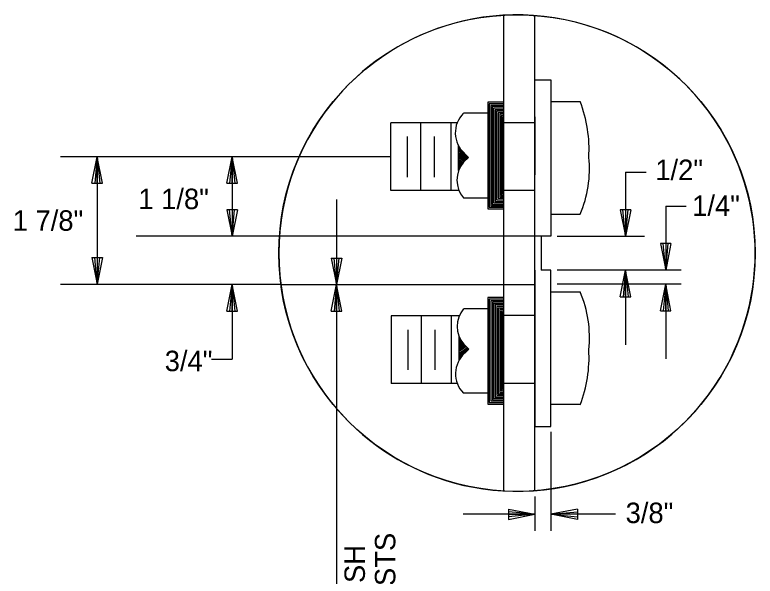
# Model space of a CAD drawing. Extents: x 12.3 to 19.6, y 18.8 to 29.6.
# Drawn here: x 12.414 to 14.586, y 27.691 to 29.338 of the extents above; entities that cross this region are included whole.
import ezdxf

# ---------------------------------------------------------------- set-up
doc = ezdxf.new("R2010")
doc.units = 0
for name, color, linetype in [('BORD-LINE', 7, 'Continuous'), ('DETL-DIMS', 7, 'Continuous'), ('DETL-LINE', 7, 'Continuous')]:
    doc.layers.add(name, color=color, linetype=linetype)

msp = doc.modelspace()

# ---------------------------------------------------------------- linework, layer by layer
at = {"layer": 'BORD-LINE'}
msp.add_lwpolyline([(14.5857, 28.6389), (14.5853, 28.6633), (14.584, 28.6882), (14.5817, 28.7135), (14.5785, 28.7392), (14.5742, 28.7652), (14.5688, 28.7915), (14.5623, 28.818), (14.5547, 28.8447), (14.5459, 28.8715), (14.5358, 28.8982), (14.5245, 28.9249), (14.5119, 28.9515), (14.498, 28.9779), (14.4828, 29.0039), (14.4663, 29.0295), (14.4485, 29.0547), (14.4295, 29.0792), (14.4092, 29.1031), (14.3877, 29.1262), (14.365, 29.1485), (14.3413, 29.1698), (14.3164, 29.19), (14.2906, 29.2092), (14.2639, 29.2272), (14.2363, 29.244), (14.208, 29.2595), (14.1791, 29.2736), (14.1495, 29.2864), (14.1196, 29.2978), (14.0892, 29.3077), (14.0586, 29.3162), (14.0279, 29.3233), (13.997, 29.3289), (13.9663, 29.3331), (13.9356, 29.3359), (13.9052, 29.3374), (13.875, 29.3375), (13.8453, 29.3364), (13.8159, 29.334), (13.7871, 29.3305), (13.7589, 29.3258), (13.7313, 29.3201), (13.7044, 29.3134), (13.6782, 29.3057), (13.6528, 29.2972), (13.6281, 29.2879), (13.6042, 29.2779), (13.5812, 29.2672), (13.559, 29.2559), (13.5376, 29.244), (13.5166, 29.2314), (13.4957, 29.2178), (13.4749, 29.2032), (13.4543, 29.1876), (13.4339, 29.1709), (13.4138, 29.1531), (13.3941, 29.1342), (13.3749, 29.1143), (13.3561, 29.0932), (13.338, 29.0711), (13.3205, 29.048), (13.3038, 29.0237), (13.2879, 28.9985), (13.2729, 28.9724), (13.259, 28.9453), (13.2461, 28.9173), (13.2343, 28.8886), (13.2238, 28.859), (13.2145, 28.8289), (13.2066, 28.7981), (13.2, 28.7669), (13.1949, 28.7352), (13.1912, 28.7033), (13.189, 28.6711), (13.1882, 28.6389), (13.189, 28.6066), (13.1912, 28.5745), (13.1949, 28.5425), (13.2, 28.5109), (13.2066, 28.4796), (13.2145, 28.4489), (13.2238, 28.4187), (13.2343, 28.3892), (13.2461, 28.3605), (13.259, 28.3325), (13.2729, 28.3054), (13.2879, 28.2792), (13.3038, 28.254), (13.3205, 28.2298), (13.338, 28.2067), (13.3561, 28.1845), (13.3749, 28.1635), (13.3941, 28.1436), (13.4138, 28.1247), (13.4339, 28.1069), (13.4543, 28.0902), (13.4749, 28.0745), (13.4957, 28.0599), (13.5166, 28.0464), (13.5376, 28.0338), (13.559, 28.0219), (13.5812, 28.0106), (13.6042, 27.9999), (13.6281, 27.9899), (13.6528, 27.9806), (13.6782, 27.9721), (13.7044, 27.9644), (13.7313, 27.9577), (13.7589, 27.952), (13.7871, 27.9473), (13.8159, 27.9438), (13.8453, 27.9414), (13.875, 27.9403), (13.9052, 27.9404), (13.9356, 27.9418), (13.9663, 27.9447), (13.997, 27.9489), (14.0279, 27.9545), (14.0586, 27.9616), (14.0892, 27.9701), (14.1196, 27.98), (14.1495, 27.9914), (14.1791, 28.0041), (14.208, 28.0183), (14.2363, 28.0338), (14.2639, 28.0505), (14.2906, 28.0685), (14.3164, 28.0877), (14.3413, 28.108), (14.365, 28.1293), (14.3877, 28.1516), (14.4092, 28.1747), (14.4295, 28.1985), (14.4485, 28.2231), (14.4663, 28.2482), (14.4828, 28.2739), (14.498, 28.2999), (14.5119, 28.3263), (14.5245, 28.3528), (14.5358, 28.3795), (14.5459, 28.4063), (14.5547, 28.4331), (14.5623, 28.4597), (14.5688, 28.4863), (14.5742, 28.5125), (14.5785, 28.5386), (14.5817, 28.5642), (14.584, 28.5895), (14.5853, 28.6144)], close=True, dxfattribs=at)
msp.add_circle((13.887, 28.6389), 0.6987, dxfattribs=at)
at = {"layer": 'DETL-DIMS'}
for p, q in [((13.5165, 28.9215), (12.5474, 28.9215)), ((12.6398, 28.8436), (12.6554, 28.9215)), ((12.6554, 28.9215), (12.6482, 28.8436)), ((12.6554, 28.8436), (12.6554, 28.9215)), ((12.671, 28.8436), (12.6554, 28.9215)), ((12.6554, 28.9215), (12.6632, 28.8436)), ((12.6554, 28.9215), (12.6554, 28.5465)), ((13.0355, 28.8436), (13.0511, 28.9215)), ((13.0511, 28.9215), (13.0439, 28.8436)), ((13.0511, 28.9215), (13.0511, 28.6882)), ((13.0511, 28.8436), (13.0511, 28.9215)), ((13.0667, 28.8436), (13.0511, 28.9215)), ((13.0511, 28.9215), (13.0589, 28.8436)), ((14.2056, 28.8763), (14.2056, 28.6882)), ((14.2056, 28.8763), (14.2656, 28.8763)), ((12.6398, 28.8436), (12.671, 28.8436)), ((13.0355, 28.8436), (13.0667, 28.8436)), ((13.3576, 28.7965), (13.3576, 27.1228)), ((13.0667, 28.7661), (13.0355, 28.7661)), ((13.0355, 28.7661), (13.0511, 28.6882)), ((13.0511, 28.6882), (13.0433, 28.7661)), ((13.0511, 28.7661), (13.0511, 28.6882)), ((13.0667, 28.7661), (13.0511, 28.6882)), ((13.0511, 28.6882), (13.0583, 28.7661)), ((14.2212, 28.7661), (14.19, 28.7661)), ((14.19, 28.7661), (14.2056, 28.6882)), ((14.2056, 28.6882), (14.1978, 28.7661)), ((14.2056, 28.7661), (14.2056, 28.6882)), ((14.2212, 28.7661), (14.2056, 28.6882)), ((14.2056, 28.6882), (14.2128, 28.7661)), ((14.3231, 28.7769), (14.3231, 28.5888)), ((14.3231, 28.7769), (14.3831, 28.7769)), ((13.9575, 28.6882), (12.7703, 28.6882)), ((14.0047, 28.6882), (14.261, 28.6882)), ((14.3387, 28.6667), (14.3075, 28.6667)), ((14.3075, 28.6667), (14.3231, 28.5888)), ((14.3231, 28.5888), (14.3153, 28.6667)), ((14.3231, 28.6667), (14.3231, 28.5888)), ((14.3387, 28.6667), (14.3231, 28.5888)), ((14.3231, 28.5888), (14.3303, 28.6667)), ((12.6398, 28.6256), (12.671, 28.6256)), ((12.6398, 28.6256), (12.6554, 28.5477)), ((12.6554, 28.5477), (12.6482, 28.6256)), ((12.6554, 28.6256), (12.6554, 28.5477)), ((12.671, 28.6256), (12.6554, 28.5477)), ((12.6554, 28.5477), (12.6632, 28.6256)), ((13.342, 28.6244), (13.3732, 28.6244)), ((13.342, 28.6244), (13.3576, 28.5465)), ((13.3576, 28.5465), (13.3504, 28.6244)), ((13.3576, 28.6244), (13.3576, 28.5465)), ((13.3732, 28.6244), (13.3576, 28.5465)), ((13.3576, 28.5465), (13.3654, 28.6244)), ((14.369, 28.5888), (14.0047, 28.5888)), ((14.19, 28.5109), (14.2056, 28.5888)), ((14.2056, 28.5888), (14.1984, 28.5109)), ((14.2056, 28.5109), (14.2056, 28.5888)), ((14.2212, 28.5109), (14.2056, 28.5888)), ((14.2056, 28.5888), (14.2134, 28.5109)), ((14.2056, 28.5888), (14.2056, 28.3697)), ((13.1944, 28.5465), (12.5474, 28.5465)), ((13.0355, 28.4686), (13.0511, 28.5465)), ((13.0511, 28.5465), (13.0439, 28.4686)), ((13.0511, 28.4686), (13.0511, 28.5465)), ((13.0667, 28.4686), (13.0511, 28.5465)), ((13.0511, 28.5465), (13.0589, 28.4686)), ((13.0511, 28.5465), (13.0511, 28.3274)), ((13.342, 28.4686), (13.3576, 28.5465)), ((13.3576, 28.5465), (13.3504, 28.4686)), ((13.3576, 28.4686), (13.3576, 28.5465)), ((13.3732, 28.4686), (13.3576, 28.5465)), ((13.3576, 28.5465), (13.3654, 28.4686)), ((14.369, 28.5477), (14.0047, 28.5477)), ((14.3075, 28.4698), (14.3231, 28.5477)), ((14.3231, 28.5477), (14.3159, 28.4698)), ((14.3231, 28.4698), (14.3231, 28.5477)), ((14.3387, 28.4698), (14.3231, 28.5477)), ((14.3231, 28.5477), (14.3309, 28.4698)), ((14.3231, 28.5477), (14.3231, 28.3286)), ((14.19, 28.5109), (14.2212, 28.5109)), ((13.0355, 28.4686), (13.0667, 28.4686)), ((13.342, 28.4686), (13.3732, 28.4686)), ((14.3075, 28.4698), (14.3387, 28.4698)), ((12.9911, 28.3274), (13.0511, 28.3274)), ((13.9863, 28.1145), (13.9863, 27.8243)), ((13.9395, 27.9253), (13.9395, 27.8243)), ((13.8616, 27.8884), (13.8616, 27.8572)), ((13.8616, 27.8884), (13.9395, 27.8728)), ((14.0642, 27.8884), (13.9863, 27.8728)), ((14.0642, 27.8884), (14.0642, 27.8572)), ((13.9395, 27.8728), (13.7286, 27.8728)), ((13.9395, 27.8728), (13.8616, 27.88)), ((13.8616, 27.8728), (13.9395, 27.8728)), ((13.8616, 27.8572), (13.9395, 27.8728)), ((13.9395, 27.8728), (13.8616, 27.865)), ((13.9863, 27.8728), (14.0642, 27.88)), ((14.0642, 27.8728), (13.9863, 27.8728)), ((14.0642, 27.8572), (13.9863, 27.8728)), ((13.9863, 27.8728), (14.0642, 27.865)), ((14.1763, 27.8728), (13.9863, 27.8728))]:
    msp.add_line(p, q, dxfattribs=at)
at = {"layer": 'DETL-LINE'}
for p, q in [((13.8485, 27.9413), (13.8485, 29.3365)), ((13.9395, 27.9422), (13.9395, 29.3356)), ((13.9395, 29.0384), (13.9395, 28.868)), ((13.5165, 28.8226), (13.5165, 29.0204)), ((13.7117, 29.0204), (13.5165, 29.0204)), ((13.6053, 28.8226), (13.6053, 29.0192)), ((13.6939, 28.8226), (13.6939, 29.0192)), ((13.9395, 29.0204), (13.8497, 29.0204)), ((13.5655, 28.862), (13.5655, 28.9808)), ((13.6447, 28.862), (13.6447, 28.9808)), ((13.7155, 28.8814), (13.7155, 28.9532)), ((13.7443, 28.9196), (13.7155, 28.9472)), ((13.7431, 28.9184), (13.7155, 28.9424)), ((13.7417, 28.9174), (13.7155, 28.9388)), ((13.7405, 28.9148), (13.7155, 28.9328)), ((13.7383, 28.9136), (13.7155, 28.9294)), ((13.7443, 28.9196), (13.7323, 28.9316)), ((13.7357, 28.9114), (13.7155, 28.9256)), ((13.7347, 28.9088), (13.7155, 28.922)), ((13.7323, 28.9076), (13.7155, 28.9184)), ((13.7297, 28.904), (13.7155, 28.9136)), ((13.7275, 28.9016), (13.7155, 28.91)), ((13.7443, 28.9196), (13.7297, 28.9054)), ((13.7237, 28.8968), (13.7155, 28.9028)), ((13.7227, 28.8946), (13.7155, 28.8994)), ((13.7215, 28.892), (13.7155, 28.8956)), ((13.7191, 28.8896), (13.7155, 28.892)), ((13.7177, 28.886), (13.7155, 28.8886)), ((13.7263, 28.8994), (13.7167, 28.9064)), ((13.7167, 28.8836), (13.7155, 28.8848)), ((13.7167, 28.8226), (13.5165, 28.8226)), ((13.9395, 28.8226), (13.8497, 28.8226)), ((13.9395, 28.6942), (13.9395, 28.8178)), ((13.9575, 28.6882), (13.9575, 28.5888)), ((13.9395, 28.5888), (13.9395, 28.5852)), ((13.1944, 28.5465), (13.9395, 28.5465)), ((13.5177, 28.4544), (13.5177, 28.2566)), ((13.7177, 28.4544), (13.5177, 28.4544)), ((13.6063, 28.4544), (13.6063, 28.2566)), ((13.6939, 28.4544), (13.6939, 28.2566)), ((13.9395, 28.4558), (13.8497, 28.4558)), ((13.5667, 28.4138), (13.5667, 28.2962)), ((13.6459, 28.4138), (13.6459, 28.2962)), ((13.7167, 28.3958), (13.7167, 28.3238)), ((13.7177, 28.3934), (13.7167, 28.3922)), ((13.7191, 28.3898), (13.7167, 28.3874)), ((13.7203, 28.3874), (13.7167, 28.3838)), ((13.7227, 28.3838), (13.7167, 28.379)), ((13.7237, 28.3814), (13.7167, 28.3766)), ((13.7251, 28.379), (13.7167, 28.373)), ((13.7275, 28.3766), (13.7167, 28.3694)), ((13.7287, 28.3742), (13.7167, 28.3658)), ((13.7311, 28.3718), (13.7167, 28.3622)), ((13.7335, 28.3694), (13.7167, 28.3586)), ((13.7347, 28.367), (13.7167, 28.355)), ((13.7371, 28.3658), (13.7167, 28.3514)), ((13.7383, 28.3646), (13.7167, 28.349)), ((13.7455, 28.3574), (13.7311, 28.3718)), ((13.7405, 28.361), (13.7167, 28.343)), ((13.7417, 28.3598), (13.7167, 28.3382)), ((13.7443, 28.3586), (13.7167, 28.3346)), ((13.7443, 28.3574), (13.7167, 28.3298)), ((13.7455, 28.3574), (13.7335, 28.3454)), ((13.7117, 28.2566), (13.5177, 28.2566)), ((13.9395, 28.2566), (13.8497, 28.2566))]:
    msp.add_line(p, q, dxfattribs=at)
for points in [[(13.9395, 28.6882), (13.9395, 29.1474), (13.9863, 29.1474), (13.9863, 28.6882), (13.9575, 28.6882)], [(13.8485, 29.0814), (13.8017, 29.0814), (13.8017, 28.7686), (13.8485, 28.7686)], [(14.0727, 29.0826), (13.9863, 29.0826)], [(13.8485, 29.0766), (13.8053, 29.0766), (13.8053, 28.7734), (13.8485, 28.7734)], [(13.8485, 29.0718), (13.8101, 29.0718), (13.8101, 28.777), (13.8485, 28.777)], [(13.8485, 29.0684), (13.8137, 29.0684), (13.8137, 28.7818), (13.8485, 28.7818)], [(13.8485, 29.0636), (13.8185, 29.0636), (13.8185, 28.7866), (13.8485, 28.7866)], [(13.8017, 29.0492), (13.7297, 29.0492)], [(13.8485, 29.0586), (13.8233, 29.0586), (13.8233, 28.7902), (13.8485, 28.7902)], [(13.8485, 29.0552), (13.8271, 29.0552), (13.8271, 28.795), (13.8485, 28.795)], [(13.8485, 29.0504), (13.8317, 29.0504), (13.8317, 28.7998), (13.8485, 28.7998)], [(13.8485, 29.0466), (13.8365, 29.0466), (13.8365, 28.8034), (13.8485, 28.8034)], [(13.8485, 29.0418), (13.8401, 29.0418), (13.8401, 28.808), (13.8485, 28.808)], [(13.8485, 29.0372), (13.8449, 29.0372), (13.8449, 28.8118), (13.8485, 28.8118)], [(13.7297, 28.801), (13.8017, 28.801)], [(13.9863, 28.753), (14.0727, 28.753)], [(13.9395, 28.5888), (13.9395, 28.1308), (13.9863, 28.1308), (13.9863, 28.5888), (13.9575, 28.5888)], [(13.9863, 28.5252), (14.0727, 28.5252)], [(13.8485, 28.5084), (13.8017, 28.5084), (13.8017, 28.1956), (13.8485, 28.1956)], [(13.8485, 28.5038), (13.8053, 28.5038), (13.8053, 28.2004), (13.8485, 28.2004)], [(13.8485, 28.4988), (13.8101, 28.4988), (13.8101, 28.2052), (13.8485, 28.2052)], [(13.8485, 28.4952), (13.8151, 28.4952), (13.8151, 28.2086), (13.8485, 28.2086)], [(13.7311, 28.476), (13.8017, 28.476)], [(13.8485, 28.4904), (13.8185, 28.4904), (13.8185, 28.2136), (13.8485, 28.2136)], [(13.8485, 28.487), (13.8233, 28.487), (13.8233, 28.2172), (13.8485, 28.2172)], [(13.8485, 28.482), (13.8281, 28.482), (13.8281, 28.222), (13.8485, 28.222)], [(13.8485, 28.4772), (13.8317, 28.4772), (13.8317, 28.2266), (13.8485, 28.2266)], [(13.8485, 28.4738), (13.8365, 28.4738), (13.8365, 28.2304), (13.8485, 28.2304)], [(13.8485, 28.469), (13.8401, 28.469), (13.8401, 28.2352), (13.8485, 28.2352)], [(13.8485, 28.4652), (13.8449, 28.4652), (13.8449, 28.2386), (13.8485, 28.2386)], [(13.8017, 28.228), (13.7297, 28.228)], [(14.0727, 28.1944), (13.9863, 28.1944)]]:
    msp.add_lwpolyline(points, dxfattribs=at)
for centre, radius, start, end in [((13.7142, 28.944), 0.3841, 356.3578, 21.2274), ((13.7865, 28.9916), 0.0806, 135.1028, 228.1706), ((13.7602, 28.8861), 0.3394, 336.8243, 5.6766), ((13.7915, 28.8529), 0.0806, 139.6417, 220.0725), ((13.7602, 28.3913), 0.3394, 353.9447, 23.1757), ((13.7922, 28.4239), 0.0806, 139.9275, 220.3584), ((13.7872, 28.2852), 0.0806, 131.8294, 224.8972), ((13.7142, 28.3333), 0.3841, 338.7726, 3.3087)]:
    msp.add_arc(centre, radius, start, end, dxfattribs=at)

# ---------------------------------------------------------------- texts
at = {"layer": 'BORD-LINE'}
for s, p in [('1/2"', (14.2927, 28.853)), (' 1 1/8"', (12.7539, 28.7678)), ('1/4"', (14.4008, 28.7481)), (' 1 7/8"', (12.3854, 28.7044)), ('3/4"', (12.8536, 28.2925)), ('3/8"', (14.2056, 27.8471))]:
    msp.add_text(s, height=0.06, dxfattribs=at).set_placement(p)
for s, p in [('BETWEEN POSTS', (13.5302, 27.1276)), ('MACHINE FINISH', (13.4409, 27.1276))]:
    msp.add_text(s, height=0.06, rotation=90, dxfattribs=at).set_placement(p)

doc.saveas('drawing.dxf')
